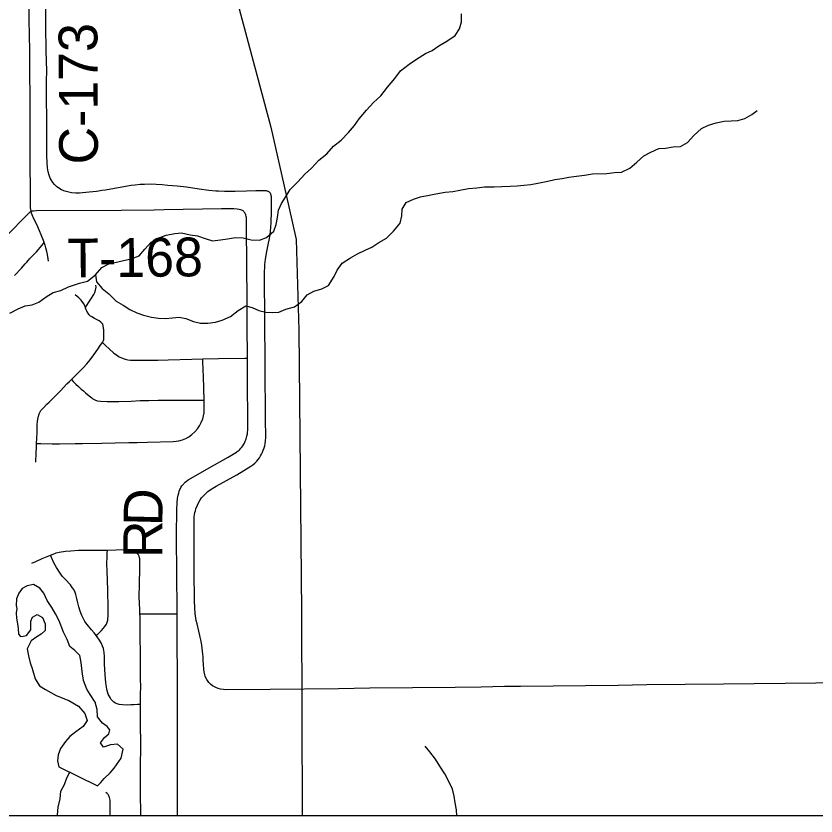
# Model space of a CAD drawing. Extents: x 0 to 34, y 0 to 22.
# Drawn here: x 9.741 to 12.669, y 4.299 to 7.227 of the extents above; entities that cross this region are included whole.
import ezdxf

# ---------------------------------------------------------------- set-up
doc = ezdxf.new("R2010")
doc.units = 0
for name, color, linetype in [('GM_X_County_Road', 7, 'Continuous'), ('GM_X_County_Road_Text', 7, 'Continuous'), ('GM_X_Minor_Lake', 7, 'Continuous'), ('GM_X_Minor_River', 7, 'Continuous'), ('GM_X_Rail_Line', 7, 'Continuous'), ('GM_X_Township_Road', 7, 'Continuous'), ('GM_X_Township_Road_Text', 7, 'Continuous'), ('SH_Text', 7, 'Continuous')]:
    doc.layers.add(name, color=color, linetype=linetype)

msp = doc.modelspace()

# ---------------------------------------------------------------- linework, layer by layer
at = {"layer": 'GM_X_County_Road'}
for points in [[(9.7961, 6.5121), (9.7948, 6.519), (9.7942, 6.5255), (9.7939, 6.5334), (9.7927, 6.7392), (9.7926, 6.8494), (9.7913, 7.1009), (9.7896, 7.213), (9.7895, 7.254)], [(9.7141, 6.4311), (9.7743, 6.4916), (9.7852, 6.5035), (9.7889, 6.5072), (9.7926, 6.5103), (9.7961, 6.5121)], [(9.8442, 6.3978), (9.8414, 6.406), (9.833, 6.4264), (9.8269, 6.4412), (9.8171, 6.4637), (9.8062, 6.485), (9.8, 6.4988), (9.7978, 6.5052), (9.7961, 6.5121)], [(9.7857, 6.3323), (9.7874, 6.3342), (9.7906, 6.3377), (9.7993, 6.3473), (9.8153, 6.3641), (9.8365, 6.3888), (9.8442, 6.3978)], [(9.8602, 6.3294), (9.859, 6.3379), (9.8566, 6.3537), (9.8542, 6.3653), (9.8505, 6.3786), (9.8475, 6.3884), (9.8442, 6.3978)], [(9.7359, 6.2769), (9.7604, 6.3045), (9.7747, 6.3201), (9.7807, 6.3267), (9.7857, 6.3323)], [(9.9947, 6.16), (9.9983, 6.1657), (10.0094, 6.1829), (10.0167, 6.1943), (10.0254, 6.2081), (10.0265, 6.2099), (10.029, 6.2148), (10.0323, 6.2233), (10.0331, 6.2282), (10.0338, 6.2347), (10.0331, 6.242)], [(9.9947, 6.16), (9.994, 6.1621), (9.9931, 6.1653), (9.99, 6.1719), (9.9859, 6.1784), (9.9793, 6.1869), (9.9702, 6.195), (9.9571, 6.2062)], [(10.0573, 6.0317), (10.0612, 6.0388), (10.0624, 6.0432), (10.0629, 6.0507), (10.0627, 6.0639), (10.0624, 6.0721), (10.0621, 6.0781), (10.0616, 6.0841), (10.0601, 6.0931), (10.0583, 6.0986), (10.0556, 6.1022), (10.0512, 6.1065), (10.0449, 6.1111), (10.0384, 6.1149), (10.0282, 6.12), (10.0183, 6.1258), (10.0136, 6.129), (10.009, 6.1332), (10.0056, 6.1374), (9.9999, 6.1469), (9.9981, 6.1511), (9.9953, 6.1582), (9.9947, 6.16)], [(9.9438, 5.8963), (9.9494, 5.9016), (9.9637, 5.9167), (9.9875, 5.9405), (9.9995, 5.9536), (10.0119, 5.9684), (10.0253, 5.9868), (10.0405, 6.008), (10.0492, 6.0208), (10.0573, 6.0317)], [(10.0573, 6.0317), (10.0688, 6.0214), (10.0818, 6.0095), (10.0994, 5.9932), (10.1082, 5.9865), (10.119, 5.98), (10.1304, 5.9744), (10.1398, 5.971), (10.1503, 5.9692), (10.1596, 5.9679), (10.1691, 5.9673), (10.1924, 5.9669), (10.2141, 5.9675), (10.2604, 5.9677), (10.2977, 5.9686), (10.3845, 5.9709), (10.4247, 5.9721)], [(10.4247, 5.9721), (10.4823, 5.9737), (10.5789, 5.975), (10.588, 5.9751)], [(10.4295, 5.8207), (10.4294, 5.8349), (10.4288, 5.8502), (10.428, 5.8654), (10.4265, 5.9072), (10.4256, 5.9315), (10.4249, 5.9639), (10.4247, 5.9721)], [(9.8157, 5.6625), (9.8167, 5.6821), (9.8178, 5.7013), (9.8186, 5.7172), (9.8188, 5.731), (9.8201, 5.7434), (9.8206, 5.7519), (9.8228, 5.7619), (9.8252, 5.7711), (9.8322, 5.7826), (9.8414, 5.7932), (9.8535, 5.8059), (9.8619, 5.8142), (9.868, 5.8201), (9.8841, 5.8359), (9.9031, 5.8551), (9.9274, 5.8808), (9.9362, 5.8893), (9.9438, 5.8963)], [(9.9438, 5.8963), (9.9501, 5.8898), (9.9604, 5.8791), (9.9692, 5.8711), (9.9795, 5.8615), (9.9879, 5.8546), (9.9955, 5.8478), (10.0085, 5.8371), (10.0178, 5.8293), (10.0226, 5.8264), (10.029, 5.8226), (10.0378, 5.8191), (10.0504, 5.8172), (10.0741, 5.8157), (10.1008, 5.8157), (10.1176, 5.816), (10.1619, 5.8175), (10.1957, 5.8195), (10.2266, 5.8201), (10.2606, 5.8205), (10.2776, 5.8206), (10.2977, 5.8207), (10.3628, 5.8207), (10.3936, 5.8206), (10.4089, 5.8206), (10.4295, 5.8207)], [(9.8157, 5.6625), (9.8322, 5.6621), (9.8729, 5.6612), (9.9004, 5.6608), (9.9579, 5.6619), (9.9843, 5.662), (10.0553, 5.6634), (10.1038, 5.6653), (10.1542, 5.666), (10.1839, 5.6664), (10.2217, 5.6671), (10.3158, 5.6693), (10.3267, 5.6705), (10.3373, 5.6725), (10.3508, 5.6761), (10.3623, 5.6809), (10.3732, 5.6869), (10.3845, 5.6951), (10.3959, 5.7056), (10.4051, 5.7162), (10.412, 5.7265), (10.4184, 5.7388), (10.4245, 5.7531), (10.4275, 5.7636), (10.4291, 5.7743), (10.4298, 5.7883), (10.4295, 5.8207)], [(9.8139, 5.5939), (9.8149, 5.628), (9.8157, 5.6466), (9.8156, 5.6589), (9.8157, 5.6625)]]:
    msp.add_lwpolyline(points, dxfattribs=at)
at = {"layer": 'GM_X_Minor_Lake'}
msp.add_line((9.8978, 4.4789), (10.0387, 4.4093), dxfattribs=at)
msp.add_lwpolyline([(10.0387, 4.4093), (10.0518, 4.4218), (10.064, 4.4362), (10.0855, 4.4574), (10.0996, 4.4737), (10.1256, 4.511), (10.1329, 4.5443), (10.1128, 4.5621), (10.0863, 4.5599), (10.0608, 4.5511), (10.0502, 4.5671), (10.0652, 4.5862), (10.0802, 4.5997), (10.0847, 4.6149), (10.0751, 4.6262), (10.057, 4.6393), (10.0387, 4.6619), (10.0384, 4.6894), (10.0306, 4.7159), (10.0123, 4.7432), (9.9997, 4.7639), (9.988, 4.7951), (9.9829, 4.8283), (9.9788, 4.8615), (9.9747, 4.887), (9.9556, 4.9048), (9.9383, 4.9198), (9.9276, 4.9453), (9.915, 4.9718), (9.8994, 5.0134), (9.8849, 5.0388), (9.8714, 5.0624), (9.855, 5.0878), (9.8424, 5.1152), (9.828, 5.1331), (9.8052, 5.1461), (9.7815, 5.142), (9.7637, 5.1314), (9.7515, 5.1141), (9.7423, 5.0941), (9.7416, 5.0694), (9.7436, 5.059), (9.7419, 5.0428), (9.7421, 5.0229), (9.7462, 5.003), (9.7492, 4.985), (9.7504, 4.9651), (9.7571, 4.9557), (9.7675, 4.9568), (9.7788, 4.9597), (9.7956, 4.9799), (9.7954, 4.9998), (9.7953, 5.0121), (9.8008, 5.0264), (9.8187, 5.0371), (9.8377, 5.0259), (9.8475, 5.0023), (9.8477, 4.9786), (9.8327, 4.9651), (9.8168, 4.9545), (9.7961, 4.94), (9.7813, 4.9113), (9.7863, 4.8848), (9.7923, 4.8602), (9.8001, 4.8394), (9.8109, 4.8006), (9.8263, 4.7761), (9.8483, 4.7621), (9.8873, 4.7398), (9.9339, 4.7223), (9.9692, 4.7009), (9.9922, 4.6746), (10.001, 4.6481), (9.9861, 4.6271), (9.9598, 4.6068), (9.9382, 4.5895), (9.9214, 4.5722), (9.9037, 4.5464), (9.8954, 4.5225), (9.8928, 4.5007), (9.8978, 4.4789)], dxfattribs=at)
at = {"layer": 'GM_X_Minor_River'}
for points in [[(11.1269, 6.9983), (11.1484, 7.0261), (11.1803, 7.0502), (11.2066, 7.0695), (11.2395, 7.0898), (11.264, 7.1005), (11.2885, 7.1179), (11.3176, 7.1353), (11.3477, 7.1556), (11.3635, 7.1805), (11.3708, 7.2052), (11.3714, 7.2347)], [(9.7183, 6.1399), (9.7493, 6.1554), (9.7738, 6.1661), (9.8003, 6.1702), (9.8248, 6.1791), (9.8511, 6.1993), (9.8774, 6.2148), (9.9048, 6.2218), (9.9331, 6.2354), (9.9727, 6.2492), (10.0029, 6.2562), (10.032, 6.2802), (10.0554, 6.3061), (10.0836, 6.3207), (10.1082, 6.3257), (10.1346, 6.3317), (10.162, 6.3378), (10.1912, 6.3495), (10.2118, 6.3734), (10.2351, 6.3994), (10.2615, 6.4139), (10.2907, 6.4247), (10.3219, 6.4307), (10.3465, 6.4329), (10.3788, 6.4267), (10.4053, 6.4222), (10.4329, 6.4131), (10.4595, 6.4039), (10.4888, 6.408), (10.5153, 6.4121), (10.5436, 6.4163), (10.572, 6.4156), (10.6015, 6.4075), (10.6318, 6.4069), (10.6582, 6.4167), (10.6844, 6.4397), (10.6936, 6.4645), (10.6981, 6.4893), (10.7016, 6.5168), (10.7127, 6.5407), (10.7266, 6.5646), (10.7443, 6.5923), (10.7724, 6.6202), (10.7976, 6.648), (10.8229, 6.6701), (10.8491, 6.6989), (10.8782, 6.723), (10.9034, 6.7508), (10.9307, 6.7729), (10.9578, 6.8008), (10.9802, 6.8267), (10.997, 6.8506), (11.0232, 6.8822), (11.0494, 6.9101), (11.0765, 6.9351), (11.1008, 6.9667), (11.1269, 6.9983)], [(10.032, 6.2802), (10.036, 6.2546), (10.0562, 6.2302), (10.0801, 6.2106), (10.1069, 6.1833), (10.1326, 6.1684), (10.1574, 6.1526), (10.1831, 6.1406), (10.2079, 6.1323), (10.2373, 6.1251), (10.2629, 6.1206), (10.2875, 6.12), (10.3131, 6.1222), (10.3377, 6.1243), (10.3623, 6.1199), (10.3909, 6.1088), (10.4165, 6.1025), (10.443, 6.1028), (10.4704, 6.1069), (10.4949, 6.1138), (10.526, 6.1275), (10.5542, 6.1497), (10.5815, 6.1661), (10.6052, 6.1598), (10.629, 6.1496), (10.6546, 6.1432), (10.6783, 6.1416), (10.7029, 6.1429), (10.7284, 6.1536), (10.7595, 6.1625), (10.7867, 6.1818), (10.8064, 6.2067), (10.8308, 6.2203), (10.8601, 6.2282), (10.8846, 6.2409), (10.905, 6.2734), (10.9161, 6.2972), (10.9348, 6.3221), (10.9648, 6.3424), (10.9912, 6.357), (11.0185, 6.3706), (11.043, 6.3813), (11.0684, 6.3977), (11.0966, 6.4142), (11.1228, 6.4392), (11.1462, 6.4689), (11.1525, 6.4955), (11.1541, 6.5202), (11.169, 6.5441), (11.1954, 6.5568), (11.2218, 6.5647), (11.2529, 6.5717), (11.2775, 6.5758), (11.3115, 6.5819), (11.339, 6.5851), (11.3654, 6.5892), (11.3975, 6.5952), (11.4269, 6.5984), (11.4552, 6.6016), (11.4912, 6.602), (11.5186, 6.6033), (11.5489, 6.6046), (11.5745, 6.6049), (11.5991, 6.608), (11.6246, 6.6102), (11.6567, 6.6163), (11.687, 6.6224), (11.7125, 6.6284), (11.7399, 6.6325), (11.7645, 6.6366), (11.7919, 6.6407), (11.8212, 6.6448), (11.8505, 6.6499), (11.9035, 6.6505), (11.9318, 6.6547), (11.9574, 6.6559), (11.9875, 6.6705), (12.0128, 6.6926), (12.0382, 6.7157), (12.0636, 6.7283), (12.0937, 6.742), (12.1183, 6.7432), (12.1457, 6.7483), (12.1722, 6.7495), (12.1986, 6.7641), (12.221, 6.79), (12.2491, 6.8159), (12.2755, 6.8276), (12.3029, 6.8365), (12.3322, 6.8416), (12.3577, 6.8428), (12.3823, 6.8441), (12.4087, 6.852), (12.4341, 6.8665), (12.4539, 6.881)], [(11.3548, 4.2991), (11.3529, 4.3213), (11.3479, 4.3469), (11.3439, 4.3715), (11.3388, 4.3971), (11.3243, 4.4273), (11.3098, 4.4537), (11.2915, 4.482), (11.2761, 4.5074), (11.2549, 4.5337), (11.2386, 4.5544)], [(9.8929, 4.2991), (9.8932, 4.3032), (9.8947, 4.3317), (9.9029, 4.3622), (9.9054, 4.3898), (9.9184, 4.4146), (9.9267, 4.4384), (9.9378, 4.4592)]]:
    msp.add_lwpolyline(points, dxfattribs=at)
at = {"layer": 'GM_X_Rail_Line'}
msp.add_lwpolyline([(13.679, 9.1945), (13.621, 9.1905), (12.7402, 9.186), (12.6286, 9.1722), (12.5249, 9.152), (12.4146, 9.1345), (12.3152, 9.1085), (12.0781, 9.0427), (11.1674, 8.8145), (10.5192, 8.6466), (10.4379, 8.6128), (10.3876, 8.5764), (10.3558, 8.5235), (10.3194, 8.4503), (10.3134, 8.3711), (10.3126, 8.279), (10.5396, 7.323), (10.674, 6.8202), (10.7391, 6.5291), (10.7656, 6.4088), (10.7761, 6.0767), (10.7857, 5.0468), (10.7878, 4.2991)], dxfattribs=at)
at = {"layer": 'GM_X_Township_Road'}
for points in [[(10.6757, 6.5212), (10.6758, 6.5361), (10.6759, 6.5576), (10.6757, 6.5654), (10.6753, 6.5688), (10.6746, 6.5715), (10.6736, 6.5744), (10.6723, 6.5771), (10.6706, 6.5796), (10.6684, 6.5817), (10.6661, 6.5834), (10.6639, 6.5847), (10.6615, 6.5855), (10.6596, 6.5861), (10.6572, 6.5867), (10.6509, 6.5873), (10.6385, 6.5877), (10.6183, 6.5872), (10.5842, 6.5859), (10.5424, 6.5847), (10.5222, 6.5845), (10.5129, 6.5846), (10.5036, 6.5848), (10.4819, 6.5857), (10.4726, 6.5863), (10.4463, 6.5886), (10.4109, 6.5934), (10.3648, 6.6), (10.3308, 6.6039), (10.2971, 6.607), (10.2756, 6.6089), (10.2533, 6.6105), (10.2316, 6.6111), (10.2117, 6.6109), (10.1947, 6.6101), (10.1774, 6.6084), (10.1623, 6.6062), (10.1286, 6.6006), (10.069, 6.5901), (10.0553, 6.5879), (10.0431, 6.5861), (10.0354, 6.585), (10.0092, 6.5818), (9.9845, 6.5796), (9.9736, 6.5788), (9.9597, 6.5787), (9.9442, 6.5802), (9.9336, 6.5822), (9.9245, 6.5845), (9.9157, 6.5875), (9.9073, 6.5914), (9.8979, 6.5969), (9.8891, 6.6034), (9.8812, 6.6108), (9.8753, 6.618), (9.8694, 6.6271), (9.8659, 6.634), (9.862, 6.6441), (9.8589, 6.6562), (9.8564, 6.6715), (9.8548, 6.6901), (9.8539, 6.7149), (9.8537, 6.7506), (9.8536, 6.7832), (9.8536, 6.8128), (9.8534, 6.8329), (9.8526, 6.9444), (9.853, 6.9893), (9.8531, 7.0265), (9.8523, 7.0622), (9.8513, 7.1026), (9.8501, 7.1879), (9.85, 7.3088)], [(9.7961, 6.5121), (9.8005, 6.5135), (9.8054, 6.5143), (9.8153, 6.5148), (10.1261, 6.5168), (10.2467, 6.5182), (10.2833, 6.5188), (10.4928, 6.5227), (10.5244, 6.5229), (10.5384, 6.5226), (10.5499, 6.5218), (10.5579, 6.5205), (10.5622, 6.5191), (10.5652, 6.5179), (10.568, 6.5164), (10.5708, 6.5146), (10.5729, 6.5129), (10.5743, 6.5116), (10.5764, 6.5093), (10.5774, 6.5079)], [(12.8744, 4.7863), (12.6682, 4.7848), (12.3297, 4.7815), (12.0495, 4.7791), (11.9441, 4.7771), (11.5871, 4.7726), (11.5281, 4.7725), (11.4427, 4.7704), (11.348, 4.7694), (11.0358, 4.7664), (10.9217, 4.7648), (10.6707, 4.7626), (10.5093, 4.7614), (10.5, 4.7622), (10.4893, 4.7637), (10.4803, 4.7662), (10.4716, 4.7693), (10.4674, 4.7713), (10.4595, 4.7761), (10.4522, 4.7819), (10.4468, 4.7874), (10.4439, 4.791), (10.4387, 4.7988), (10.4347, 4.8071), (10.4332, 4.8113), (10.4318, 4.8159), (10.4295, 4.8265), (10.4283, 4.8357), (10.4269, 4.8542), (10.4263, 4.8682), (10.4255, 4.8806), (10.4247, 4.8929), (10.4239, 4.9007), (10.4223, 4.9145), (10.4198, 4.9314), (10.4174, 4.9435), (10.4152, 4.9541), (10.4138, 4.9602), (10.4102, 4.9753), (10.4035, 5.0024), (10.4008, 5.0145), (10.3994, 5.0237), (10.397, 5.0406), (10.3951, 5.0607), (10.3939, 5.0871), (10.3938, 5.0979), (10.3936, 5.1212), (10.3935, 5.1601), (10.3931, 5.2144), (10.3927, 5.3714), (10.3927, 5.3836), (10.3932, 5.3926), (10.3943, 5.4023), (10.3956, 5.4093), (10.3972, 5.4161), (10.3996, 5.4235), (10.405, 5.4371), (10.4088, 5.4452), (10.414, 5.4542), (10.4197, 5.463), (10.4255, 5.4698), (10.4329, 5.4772), (10.4384, 5.4823), (10.4434, 5.4864), (10.4513, 5.4926), (10.4616, 5.4991), (10.4733, 5.5064), (10.5487, 5.5482), (10.6002, 5.5791), (10.6079, 5.5848), (10.6149, 5.5907), (10.6217, 5.5981), (10.6269, 5.6043), (10.6318, 5.6104), (10.6357, 5.6168), (10.6392, 5.6229), (10.6432, 5.6308), (10.646, 5.6382), (10.6489, 5.647), (10.6513, 5.654), (10.6526, 5.661), (10.6537, 5.6718), (10.6546, 5.6847), (10.6542, 5.7522), (10.6531, 5.9426), (10.6511, 6.1261), (10.6507, 6.2632), (10.6505, 6.2798), (10.6507, 6.2932), (10.6512, 6.3055), (10.6519, 6.3176), (10.6545, 6.3376), (10.6594, 6.3651), (10.6654, 6.3956), (10.6674, 6.4063), (10.6707, 6.4262), (10.6722, 6.44), (10.6733, 6.454), (10.6741, 6.4715), (10.6756, 6.5113), (10.6757, 6.5212)], [(10.588, 5.9751), (10.5874, 6.0958), (10.5868, 6.1849), (10.5846, 6.4521), (10.5845, 6.4809), (10.5842, 6.486), (10.5841, 6.4878), (10.5839, 6.4897), (10.5834, 6.4932), (10.582, 6.4984), (10.5814, 6.5001), (10.5798, 6.5034), (10.5783, 6.5066), (10.5774, 6.5079)], [(10.3304, 5.0394), (10.3303, 5.0674), (10.3297, 5.1721), (10.3288, 5.3332), (10.3292, 5.4135), (10.3297, 5.4275), (10.3301, 5.4388), (10.3306, 5.4468), (10.3312, 5.4527), (10.3315, 5.4554), (10.3321, 5.4599), (10.3324, 5.4623), (10.3333, 5.4673), (10.3345, 5.4731), (10.3363, 5.4808), (10.3386, 5.4882), (10.3408, 5.4938), (10.3427, 5.4978), (10.3447, 5.5016), (10.3479, 5.5069), (10.3514, 5.5115), (10.3546, 5.5152), (10.3569, 5.5176), (10.3599, 5.5204), (10.3648, 5.5244), (10.3712, 5.5289), (10.3818, 5.5355), (10.4479, 5.5729), (10.517, 5.6124), (10.5413, 5.6267), (10.5473, 5.6306), (10.5508, 5.6331), (10.5544, 5.6359), (10.5575, 5.6384), (10.56, 5.6408), (10.5637, 5.6448), (10.567, 5.6487), (10.5704, 5.6534), (10.5747, 5.6599), (10.5767, 5.6636), (10.5785, 5.6672), (10.5801, 5.6709), (10.582, 5.6756), (10.5833, 5.6795), (10.5859, 5.6892), (10.5876, 5.6978), (10.5884, 5.7037), (10.5892, 5.711), (10.5896, 5.7168), (10.5899, 5.7257), (10.5899, 5.7443), (10.5884, 5.8883), (10.588, 5.9751)], [(9.7986, 5.2243), (9.8136, 5.2308), (9.8364, 5.241), (9.8666, 5.2536), (9.8772, 5.258), (9.8879, 5.2617), (9.8986, 5.2644), (9.9217, 5.2679), (9.9417, 5.2702), (9.9695, 5.2715), (9.9831, 5.2715), (10.0277, 5.2723), (10.0548, 5.2723), (10.0757, 5.2725), (10.107, 5.2736), (10.1434, 5.2739), (10.1525, 5.2736), (10.1602, 5.2729), (10.1675, 5.2712), (10.1722, 5.2692), (10.1769, 5.2667)], [(10.035, 4.9591), (10.0383, 4.9625), (10.0534, 4.9782), (10.0654, 4.9924), (10.0715, 5.0013), (10.0746, 5.0083), (10.0764, 5.0158), (10.0777, 5.0344), (10.078, 5.0593), (10.0766, 5.1262), (10.0745, 5.196), (10.0738, 5.2208), (10.0739, 5.2496), (10.0745, 5.2609), (10.0757, 5.2725)], [(10.1966, 4.7073), (10.1853, 4.7066), (10.1736, 4.706), (10.1605, 4.7055), (10.1497, 4.7053), (10.1311, 4.7056), (10.1188, 4.707), (10.1113, 4.7091), (10.1044, 4.7124), (10.0993, 4.7158), (10.0926, 4.7222), (10.0883, 4.7272), (10.085, 4.7322), (10.0813, 4.7389), (10.0783, 4.7455), (10.0756, 4.7532), (10.0733, 4.7619), (10.0716, 4.7716), (10.0696, 4.7867), (10.067, 4.8168), (10.0652, 4.8552), (10.065, 4.8691), (10.0643, 4.8831), (10.063, 4.8981), (10.0606, 4.9124), (10.058, 4.9208), (10.0533, 4.9305), (10.046, 4.9429), (10.0383, 4.9549), (10.035, 4.9591), (10.0269, 4.9693), (10.0172, 4.9803), (10.0013, 4.9994), (9.9932, 5.0108), (9.9861, 5.0228), (9.9814, 5.0326), (9.9754, 5.0486), (9.9704, 5.065), (9.9668, 5.0787), (9.9623, 5.0996), (9.9601, 5.1098), (9.9577, 5.1165), (9.9524, 5.1275), (9.947, 5.1359), (9.94, 5.1446), (9.9204, 5.1653), (9.9104, 5.177), (9.9019, 5.188), (9.8889, 5.2092), (9.8799, 5.2256), (9.8705, 5.2453), (9.8666, 5.2536)], [(10.1974, 4.2991), (10.1971, 4.3318), (10.1968, 4.3585), (10.1968, 4.3957), (10.1969, 4.4492), (10.1969, 4.5003), (10.1972, 4.5341), (10.1971, 4.559), (10.1973, 4.5876), (10.1968, 4.6103), (10.1969, 4.6351), (10.1965, 4.6646), (10.1963, 4.6903), (10.1966, 4.7073), (10.1967, 4.7144), (10.197, 4.7432), (10.1974, 4.7732), (10.1969, 4.7994), (10.1969, 4.8445), (10.1967, 4.8647), (10.196, 4.9004), (10.1951, 4.9492), (10.1951, 4.9836), (10.195, 5.0148), (10.1948, 5.0284), (10.1945, 5.0385), (10.1941, 5.0468), (10.1935, 5.0565), (10.1925, 5.0759), (10.1922, 5.1037), (10.1926, 5.1455), (10.1942, 5.2076), (10.1943, 5.2355), (10.1939, 5.2401), (10.1932, 5.2441), (10.1916, 5.2498), (10.1892, 5.2545), (10.1866, 5.2579), (10.1836, 5.2612), (10.1802, 5.2642), (10.1769, 5.2667)], [(10.1945, 5.0385), (10.2382, 5.0389), (10.289, 5.0394), (10.3304, 5.0394)], [(10.3318, 4.2991), (10.3313, 4.4851), (10.3323, 4.621), (10.3321, 4.7723), (10.332, 4.8141), (10.331, 4.9349), (10.3304, 5.0394)], [(10.0854, 4.2991), (10.0853, 4.3063), (10.0856, 4.3421), (10.0851, 4.3569), (10.0844, 4.3623), (10.0834, 4.3663), (10.0824, 4.37), (10.0811, 4.373), (10.0781, 4.3776), (10.0748, 4.3813), (10.0697, 4.3857)]]:
    msp.add_lwpolyline(points, dxfattribs=at)
at = {"layer": 'SH_Text'}
msp.add_lwpolyline([(1.6712, 21.2991), (18.6712, 21.2991), (18.6712, 4.2991), (1.6712, 4.2991)], close=True, dxfattribs=at)

# ---------------------------------------------------------------- texts
at = {"layer": 'GM_X_County_Road_Text'}
msp.add_text('C-173', height=0.14205, rotation=90.2733, dxfattribs=at).set_placement((10.041, 6.6841))
at = {"layer": 'GM_X_Township_Road_Text'}
for s, height, rotation, p in [('T-168', 0.14205, 0.5631, (9.9293, 6.2697)), ('D', 0.142, 88.5792, (10.2759, 5.3591)), ('R', 0.142, 89.9922, (10.2759, 5.2433))]:
    msp.add_text(s, height=height, rotation=rotation, dxfattribs=at).set_placement(p)

doc.saveas('drawing.dxf')
